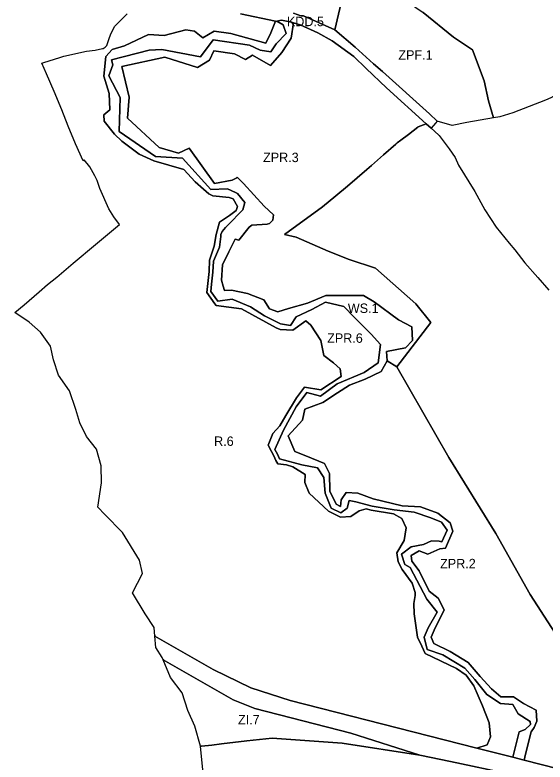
# Model space of a CAD drawing. Extents: x 7422965 to 7424741, y 5551047 to 5553849.
# Drawn here: x 7423382 to 7424058, y 5551939 to 5552892 of the extents above; entities that cross this region are included whole.
import ezdxf

# ---------------------------------------------------------------- set-up
doc = ezdxf.new("R2010")
doc.units = 0
for name, color, linetype in [('Default', 7, 'Continuous'), ('linie_rozgraniczajace', 7, 'Continuous'), ('oznaczenia_przeznaczen', 7, 'Continuous')]:
    doc.layers.add(name, color=color, linetype=linetype)

msp = doc.modelspace()

# ---------------------------------------------------------------- linework, layer by layer
at = {"layer": 'Default'}
for centre in [(7423560.61, 5552099.93), (7423571.24, 5552069.67)]:
    msp.add_circle(centre, 0.5, dxfattribs=at)
at = {"layer": 'linie_rozgraniczajace'}
for points in [[(7423790.23, 5552873.28), (7423799.43, 5552913.67), (7423849.34, 5552932.62), (7423902.73, 5552895.58), (7423941.64, 5552864.17), (7423966.03, 5552847.79), (7423980.88, 5552808.54), (7423986.42, 5552782.73), (7423992.54, 5552761.23), (7423958.43, 5552755.11), (7423939.86, 5552751.5), (7423920.85, 5552756.78), (7423910.83, 5552766.27), (7423850.81, 5552820.09), (7423839.55, 5552830.12), (7423816.12, 5552851.49)], [(7423518.12, 5552826.48), (7423573.2, 5552838.45), (7423614.8, 5552825.61), (7423630.31, 5552834.81), (7423635.93, 5552846.53), (7423662.15, 5552843.04), (7423676.01, 5552835.75), (7423684.91, 5552840.93), (7423708.24, 5552828.03), (7423722.4, 5552844.73), (7423734.34, 5552862.84), (7423737.47, 5552882.31), (7423745.99, 5552879.68), (7423768.55, 5552869.52), (7423786.65, 5552859.46), (7423814.43, 5552839.49), (7423830.33, 5552823.95), (7423856.04, 5552799.55), (7423906.82, 5552753.61), (7423900.02, 5552750.92), (7423896.58, 5552749.57), (7423896.01, 5552749.16), (7423884.16, 5552740.14), (7423874.28, 5552732.6), (7423869.69, 5552729.15), (7423868.14, 5552727.71), (7423852.28, 5552713.95), (7423836.83, 5552700.56), (7423830.95, 5552695.39), (7423806.47, 5552674.23), (7423791.37, 5552661.63), (7423774.44, 5552647.52), (7423725.87, 5552612.31), (7423740.76, 5552608.81), (7423781.67, 5552591), (7423808.46, 5552580.55), (7423841.86, 5552569.28), (7423893.7, 5552523.72), (7423912.7, 5552500.05), (7423869.36, 5552443.65), (7423856.77, 5552451.18), (7423856.17, 5552463.3), (7423880.19, 5552467.96), (7423889.14, 5552477.03), (7423888.44, 5552494.7), (7423871.43, 5552503.56), (7423840.28, 5552526.39), (7423826.71, 5552534.72), (7423778.85, 5552534.43), (7423755.2, 5552524.7), (7423731.19, 5552517.98), (7423717.3, 5552513.6), (7423706.78, 5552517.34), (7423699.33, 5552529.22), (7423678.68, 5552537.06), (7423658.18, 5552541.42), (7423649.45, 5552540.81), (7423647.6, 5552546.31), (7423645.4, 5552554.18), (7423646.92, 5552573.84), (7423654.67, 5552590.42), (7423662.8, 5552606.36), (7423667.83, 5552605.2), (7423680.9, 5552621.72), (7423684.32, 5552624.34), (7423703.8, 5552625.43), (7423706.94, 5552626.59), (7423711.13, 5552630.72), (7423711.75, 5552637.44), (7423700.08, 5552648.69), (7423673.64, 5552677.54), (7423665.53, 5552685.6), (7423665.02, 5552684.74), (7423659.29, 5552681.76), (7423636.4, 5552677.47), (7423604.33, 5552722.68), (7423590.57, 5552716.14), (7423565.78, 5552723.18), (7423525.68, 5552760.58), (7423527.6, 5552787.42)], [(7423571.24, 5552069.67), (7423660.42, 5552018.69), (7423687.98, 5552007.54), (7423810.5, 5551976.35), (7423898.81, 5551948.34), (7423799.44, 5551963.27), (7423710.11, 5551969.96), (7423677.82, 5551966.24), (7423645.54, 5551962.52), (7423633.28, 5551961.11), (7423619.89, 5551959.57), (7423618.77, 5551959.44), (7423611.64, 5551985.21), (7423602.59, 5552005.1), (7423595.36, 5552027.64), (7423580.3, 5552047.19)]]:
    msp.add_lwpolyline(points, close=True, dxfattribs=at)
for points in [[(7423799.43, 5552913.67), (7423790.23, 5552873.28), (7423750.07, 5552891.5), (7423746.77, 5552891.46), (7423737.23, 5552894.78)], [(7424119.81, 5552913.52), (7424124.09, 5552863.72), (7424127.86, 5552820.64), (7424065.95, 5552786.72), (7424059.13, 5552783.75), (7424017.18, 5552767.52), (7424000.77, 5552762.43), (7423992.54, 5552761.23), (7423986.42, 5552782.73), (7423980.88, 5552808.54), (7423966.03, 5552847.79), (7423941.64, 5552864.17), (7423902.73, 5552895.58)], [(7423381.92, 5552512.9), (7423393.91, 5552522.65), (7423412.78, 5552539.16), (7423423.51, 5552548.44), (7423435.26, 5552558.04), (7423456.27, 5552575.82), (7423484.66, 5552599.8), (7423515.49, 5552625.14), (7423508.29, 5552634.78), (7423501.59, 5552645.04), (7423490.22, 5552671.15), (7423486.78, 5552681.18), (7423483.94, 5552687.27), (7423477.67, 5552698.55), (7423470.41, 5552707.71), (7423469.11, 5552706.51), (7423459.04, 5552728.14), (7423449.78, 5552750.61), (7423441.58, 5552771.2), (7423431.88, 5552794.58), (7423422.17, 5552817.19), (7423416.17, 5552830.91), (7423418.6, 5552831.93), (7423439.05, 5552838.34), (7423444.5, 5552840.06), (7423473.12, 5552846.34), (7423484.14, 5552847.66), (7423493.67, 5552849.65), (7423494.7, 5552849.78), (7423497.14, 5552851.28), (7423499, 5552853.67), (7423501.89, 5552861.11), (7423504.32, 5552868.56), (7423509.48, 5552877.98), (7423514.86, 5552883.69), (7423525.29, 5552893.69)], [(7423669.78, 5552893.7), (7423714.41, 5552884.41), (7423708.37, 5552869.78), (7423701.9, 5552856.51), (7423657.37, 5552868.71), (7423636.23, 5552871.86), (7423621.57, 5552863.26), (7423611.21, 5552871.85), (7423600.14, 5552873.4), (7423572.41, 5552866.27), (7423552.34, 5552867.46), (7423521.9, 5552853.21), (7423506.07, 5552848.57), (7423498.01, 5552839.35), (7423495.57, 5552814.53), (7423502.35, 5552792.37), (7423503.2, 5552771.39), (7423495.45, 5552765.07), (7423495.77, 5552757.08), (7423508.86, 5552740.31), (7423518.42, 5552731.31), (7423540.62, 5552714.78), (7423559.29, 5552706.32), (7423597.36, 5552695.15), (7423612, 5552679.73), (7423622.4, 5552670.14), (7423629.4, 5552664.04), (7423634.65, 5552661.74), (7423655.49, 5552659.62), (7423660.35, 5552657.76), (7423665.97, 5552648.28), (7423664.14, 5552643.17), (7423655.79, 5552636.47), (7423643.12, 5552627.95), (7423638.76, 5552612.18), (7423636.35, 5552597.65), (7423630.36, 5552579.67), (7423629.65, 5552565.36), (7423626.74, 5552538.29), (7423636.81, 5552523.95), (7423638.6, 5552521.69), (7423671.12, 5552517.5), (7423715.17, 5552493.41), (7423720.55, 5552490.99), (7423736.41, 5552490.24), (7423753.3, 5552502.32), (7423759.54, 5552496.57), (7423772.34, 5552477.07), (7423776.11, 5552458.21), (7423788.5, 5552448.71), (7423796.82, 5552441.04), (7423798.22, 5552431.09), (7423772.48, 5552414.12), (7423751.48, 5552417.61), (7423741.39, 5552404.19), (7423727.56, 5552381.39), (7423719.88, 5552368.1)], [(7423737.23, 5552894.78), (7423746.77, 5552891.46), (7423750.07, 5552891.5), (7423790.23, 5552873.28), (7423816.12, 5552851.49), (7423839.55, 5552830.12), (7423850.81, 5552820.09), (7423910.83, 5552766.27), (7423920.85, 5552756.78), (7423918.68, 5552754.4), (7423913.08, 5552747.94), (7423906.82, 5552753.61), (7423856.04, 5552799.55), (7423830.33, 5552823.95), (7423814.43, 5552839.49), (7423786.65, 5552859.46), (7423768.55, 5552869.52), (7423745.99, 5552879.68), (7423737.47, 5552882.31), (7423734.65, 5552883.18), (7423722.04, 5552885.93), (7423715.99, 5552884.44), (7423715.19, 5552884.25), (7423714.41, 5552884.41), (7423669.78, 5552893.7)], [(7423495.77, 5552757.08), (7423495.45, 5552765.07), (7423503.2, 5552771.39), (7423502.35, 5552792.37), (7423495.57, 5552814.53), (7423498.01, 5552839.35), (7423506.07, 5552848.57), (7423521.9, 5552853.21), (7423552.34, 5552867.46), (7423572.41, 5552866.27), (7423600.14, 5552873.4), (7423611.21, 5552871.85), (7423621.57, 5552863.26), (7423636.23, 5552871.86), (7423657.37, 5552868.71), (7423701.9, 5552856.51), (7423708.37, 5552869.78), (7423714.41, 5552884.41), (7423715.19, 5552884.25), (7423715.99, 5552884.44), (7423724.12, 5552879.63), (7423728.09, 5552868.86), (7423715.36, 5552855.64), (7423708.53, 5552845.33), (7423694.97, 5552847.44), (7423681.31, 5552853.85), (7423634.95, 5552860.82), (7423618.89, 5552838.84), (7423569.19, 5552848.56), (7423553, 5552847.71), (7423504.95, 5552835.26), (7423506.66, 5552828.62), (7423501.73, 5552814.95), (7423516.28, 5552787.25), (7423514.81, 5552743.76), (7423561.23, 5552711.88), (7423595.84, 5552709.54), (7423631.86, 5552669.82), (7423652.56, 5552670.42), (7423655.99, 5552669.55), (7423665.93, 5552664.56), (7423675.13, 5552653.05), (7423672.8, 5552643.86), (7423653.55, 5552624.23), (7423650.7, 5552621.08), (7423646.49, 5552616.25), (7423644.52, 5552612.31), (7423644.59, 5552610.02), (7423643.13, 5552596.36), (7423635.3, 5552578.5), (7423634.57, 5552564.46), (7423632.73, 5552549.12), (7423631.88, 5552539.69), (7423640.87, 5552527.11), (7423659.2, 5552530.04), (7423682.56, 5552520.23), (7423700.48, 5552508.65), (7423720.76, 5552498.26), (7423733.62, 5552496.4), (7423740.79, 5552507.45), (7423760.88, 5552516.48), (7423778.28, 5552526.14), (7423801.75, 5552520.67), (7423815.43, 5552506.41), (7423836.5, 5552485.18), (7423848.28, 5552471.98), (7423845.61, 5552448.56), (7423827.57, 5552436.21), (7423793.23, 5552421.73), (7423771.95, 5552405.92), (7423754.3, 5552410.96), (7423741.01, 5552392.42), (7423724.64, 5552362.81), (7423713.56, 5552337.91), (7423716.78, 5552332.11), (7423719.42, 5552326.32), (7423748.14, 5552318.52), (7423768.09, 5552314.6), (7423776.1, 5552302.24), (7423777.86, 5552282.4), (7423785.4, 5552263.16), (7423797.61, 5552257.43), (7423806.09, 5552263.18), (7423808.26, 5552273.19), (7423816.95, 5552271.36), (7423837.6, 5552265.74), (7423865.9, 5552261.08), (7423891.32, 5552258.33), (7423912.44, 5552250.92), (7423926.36, 5552245.41), (7423933.33, 5552235.37), (7423926.66, 5552220.14), (7423923.13, 5552221.11), (7423913.64, 5552221.44), (7423903.45, 5552216.88), (7423887.49, 5552214.09), (7423875.1, 5552204.48), (7423879.67, 5552191.32), (7423886.42, 5552187.66), (7423907.58, 5552147.01)], [(7423501.73, 5552814.95), (7423506.66, 5552828.62), (7423504.95, 5552835.26), (7423553, 5552847.71), (7423569.19, 5552848.56), (7423618.89, 5552838.84), (7423634.95, 5552860.82), (7423681.31, 5552853.85), (7423694.97, 5552847.44), (7423708.53, 5552845.33), (7423715.36, 5552855.64), (7423728.09, 5552868.86), (7423724.12, 5552879.63), (7423715.99, 5552884.44), (7423722.04, 5552885.93), (7423734.65, 5552883.18), (7423737.47, 5552882.31), (7423734.34, 5552862.84), (7423722.4, 5552844.73), (7423708.24, 5552828.03), (7423684.91, 5552840.93), (7423676.01, 5552835.75), (7423662.15, 5552843.04), (7423635.93, 5552846.53), (7423630.31, 5552834.81), (7423614.8, 5552825.61), (7423573.2, 5552838.45), (7423518.12, 5552826.48), (7423527.6, 5552787.42), (7423525.68, 5552760.58), (7423565.78, 5552723.18), (7423590.57, 5552716.14), (7423604.33, 5552722.68), (7423636.4, 5552677.47), (7423659.29, 5552681.76), (7423665.02, 5552684.74), (7423665.53, 5552685.6), (7423673.64, 5552677.54), (7423700.08, 5552648.69), (7423711.75, 5552637.44), (7423711.13, 5552630.72), (7423706.94, 5552626.59), (7423703.8, 5552625.43), (7423684.32, 5552624.34), (7423680.9, 5552621.72), (7423667.83, 5552605.2), (7423662.8, 5552606.36), (7423654.67, 5552590.42), (7423646.92, 5552573.84), (7423645.4, 5552554.18), (7423647.6, 5552546.31), (7423649.45, 5552540.81), (7423658.18, 5552541.42), (7423678.68, 5552537.06), (7423699.33, 5552529.22), (7423706.78, 5552517.34), (7423717.3, 5552513.6), (7423731.19, 5552517.98), (7423755.2, 5552524.7), (7423778.85, 5552534.43), (7423826.71, 5552534.72), (7423840.28, 5552526.39), (7423871.43, 5552503.56), (7423888.44, 5552494.7), (7423889.14, 5552477.03), (7423880.19, 5552467.96), (7423856.17, 5552463.3), (7423856.77, 5552451.18), (7423849.24, 5552437.64), (7423828.99, 5552427.81), (7423808.65, 5552420.26), (7423793.42, 5552410.29), (7423774.82, 5552397.91), (7423763.47, 5552393.94), (7423751.7, 5552389.44), (7423749.03, 5552375.31), (7423730.47, 5552355.5), (7423738.91, 5552335.44), (7423753, 5552330.02), (7423777.12, 5552320.16), (7423783.51, 5552307.61), (7423783.55, 5552284.87), (7423791.78, 5552268.26), (7423797.33, 5552265.52), (7423798.36, 5552273.72), (7423804.73, 5552283.13), (7423819.42, 5552282.47), (7423839.06, 5552274.98), (7423876.01, 5552266.1), (7423899.37, 5552265.11), (7423921.38, 5552256.76), (7423937.24, 5552244.36), (7423940.53, 5552233.8), (7423931.54, 5552212.19), (7423924.28, 5552211.5), (7423908.87, 5552204.75), (7423897.68, 5552208.99), (7423887.35, 5552202.71), (7423888.52, 5552195.81), (7423897.92, 5552183.41)], [(7423631.86, 5552669.82), (7423595.84, 5552709.54), (7423561.23, 5552711.88), (7423514.81, 5552743.76), (7423516.28, 5552787.25), (7423501.73, 5552814.95)], [(7423907.58, 5552147.01), (7423920.57, 5552130.57), (7423909.34, 5552110.5), (7423904, 5552098.61), (7423908.13, 5552083), (7423928.02, 5552075.95), (7423956.18, 5552059.32), (7423968.77, 5552044.8), (7423984.28, 5552025.67), (7424001.51, 5552013.86), (7424017.3, 5552012.88), (7424024.18, 5552000.72), (7424039.31, 5551991.14), (7424040.01, 5551987.27), (7424032.89, 5551980.96), (7424025.26, 5551977.97), (7424017.68, 5551947.36), (7424017.17, 5551945.4), (7423971.53, 5551957.02), (7423984.41, 5551961.28), (7423989, 5551971.47), (7423987.27, 5551989.41), (7423978.39, 5552011.07), (7423967.34, 5552036.64), (7423957.78, 5552050.26), (7423945.43, 5552058.77), (7423905.55, 5552077.93), (7423901.25, 5552087), (7423895.77, 5552098.79), (7423891.56, 5552128.64), (7423891.03, 5552141.63), (7423892.62, 5552151.7), (7423892.5, 5552154.7), (7423892.46, 5552155.7), (7423888.98, 5552167.56), (7423876.26, 5552185.06), (7423870.86, 5552194.85), (7423869.2, 5552206.23), (7423878.75, 5552222.19), (7423881.1, 5552238.3), (7423875.62, 5552250.09), (7423865.22, 5552256.12), (7423836.53, 5552260.85), (7423830.09, 5552262.25), (7423821.18, 5552259.89), (7423810.47, 5552252.45), (7423797.49, 5552251.92), (7423782.17, 5552259.31), (7423769.7, 5552270.81), (7423757.22, 5552282.31), (7423751.66, 5552296.1), (7423752.25, 5552306.13), (7423736.63, 5552315.97), (7423728.5, 5552318.32), (7423717.24, 5552319.9), (7423714.95, 5552324.08), (7423712.32, 5552329.86), (7423709.14, 5552335.56), (7423705.12, 5552343.43), (7423711.1, 5552358.5), (7423719.88, 5552368.1), (7423727.56, 5552381.39), (7423741.39, 5552404.19), (7423751.48, 5552417.61), (7423772.48, 5552414.12), (7423798.22, 5552431.09), (7423796.82, 5552441.04), (7423788.5, 5552448.71), (7423776.11, 5552458.21), (7423772.34, 5552477.07), (7423759.54, 5552496.57), (7423753.3, 5552502.32), (7423736.41, 5552490.24), (7423720.55, 5552490.99), (7423715.17, 5552493.41), (7423671.12, 5552517.5), (7423638.6, 5552521.69), (7423636.81, 5552523.95), (7423626.74, 5552538.29), (7423629.65, 5552565.36), (7423630.36, 5552579.67), (7423636.35, 5552597.65), (7423638.76, 5552612.18), (7423643.12, 5552627.95), (7423655.79, 5552636.47), (7423664.14, 5552643.17), (7423665.97, 5552648.28), (7423660.35, 5552657.76), (7423655.49, 5552659.62), (7423634.65, 5552661.74), (7423629.4, 5552664.04), (7423622.4, 5552670.14), (7423612, 5552679.73), (7423597.36, 5552695.15), (7423559.29, 5552706.32), (7423540.62, 5552714.78), (7423518.42, 5552731.31), (7423508.86, 5552740.31), (7423495.77, 5552757.08)], [(7424089.19, 5552076.05), (7424039.42, 5552153.32), (7423995.71, 5552231.1), (7423935.73, 5552327.89), (7423869.36, 5552443.65), (7423912.7, 5552500.05), (7423893.7, 5552523.72), (7423841.86, 5552569.28), (7423808.46, 5552580.55), (7423781.67, 5552591), (7423740.76, 5552608.81), (7423725.87, 5552612.31), (7423774.44, 5552647.52), (7423791.37, 5552661.63), (7423806.47, 5552674.23), (7423830.95, 5552695.39), (7423836.83, 5552700.56), (7423852.28, 5552713.95), (7423868.14, 5552727.71), (7423869.69, 5552729.15), (7423874.28, 5552732.6), (7423884.16, 5552740.14), (7423896.01, 5552749.16), (7423896.58, 5552749.57), (7423900.02, 5552750.92), (7423906.82, 5552753.61), (7423913.08, 5552747.94), (7423917.16, 5552744.25), (7423923.26, 5552738.78), (7423936.05, 5552721.84), (7423943.57, 5552710.44), (7423948.13, 5552700.78), (7423968.75, 5552667.08), (7423981.44, 5552643.95), (7423996.22, 5552621.82), (7424012.77, 5552601.21), (7424019.93, 5552592.98), (7424032.56, 5552576.3), (7424049.23, 5552557.69), (7424063.4, 5552541.4)], [(7423897.92, 5552183.41), (7423910.41, 5552157.37), (7423921.95, 5552148.62), (7423929.69, 5552133.46), (7423917.09, 5552107.71), (7423912.99, 5552098.51), (7423916.62, 5552090.57), (7423937.52, 5552080.46), (7423960.41, 5552066.2), (7423975.43, 5552048.48), (7423990, 5552032.9), (7424001.99, 5552022.6), (7424018.06, 5552022.7), (7424031.11, 5552013.9), (7424047.25, 5552005.6), (7424047.8, 5551991.71), (7424044.62, 5551983.49), (7424040.76, 5551977.72), (7424033.55, 5551949.56), (7424031.65, 5551941.72), (7424017.17, 5551945.4), (7424017.68, 5551947.36), (7424025.26, 5551977.97), (7424032.89, 5551980.96), (7424040.01, 5551987.27), (7424039.31, 5551991.14), (7424024.18, 5552000.72), (7424017.3, 5552012.88), (7424001.51, 5552013.86), (7423984.28, 5552025.67), (7423968.77, 5552044.8), (7423956.18, 5552059.32), (7423928.02, 5552075.95), (7423908.13, 5552083), (7423904, 5552098.61), (7423909.34, 5552110.5), (7423920.57, 5552130.57), (7423907.58, 5552147.01), (7423886.42, 5552187.66), (7423879.67, 5552191.32), (7423875.1, 5552204.48), (7423887.49, 5552214.09), (7423903.45, 5552216.88), (7423913.64, 5552221.44), (7423923.13, 5552221.11), (7423926.66, 5552220.14), (7423933.33, 5552235.37), (7423926.36, 5552245.41), (7423912.44, 5552250.92), (7423891.32, 5552258.33), (7423865.9, 5552261.08), (7423837.6, 5552265.74), (7423816.95, 5552271.36), (7423808.26, 5552273.19), (7423806.09, 5552263.18), (7423797.61, 5552257.43), (7423785.4, 5552263.16), (7423777.86, 5552282.4), (7423776.1, 5552302.24), (7423768.09, 5552314.6), (7423748.14, 5552318.52), (7423719.42, 5552326.32), (7423716.78, 5552332.11), (7423713.56, 5552337.91), (7423724.64, 5552362.81), (7423741.01, 5552392.42), (7423754.3, 5552410.96), (7423771.95, 5552405.92), (7423793.23, 5552421.73), (7423827.57, 5552436.21), (7423845.61, 5552448.56), (7423848.28, 5552471.98), (7423836.5, 5552485.18), (7423815.43, 5552506.41), (7423801.75, 5552520.67), (7423778.28, 5552526.14), (7423760.88, 5552516.48), (7423740.79, 5552507.45), (7423733.62, 5552496.4), (7423720.76, 5552498.26), (7423700.48, 5552508.65), (7423682.56, 5552520.23), (7423659.2, 5552530.04), (7423640.87, 5552527.11), (7423631.88, 5552539.69), (7423632.73, 5552549.12), (7423634.57, 5552564.46), (7423635.3, 5552578.5), (7423643.13, 5552596.36), (7423644.59, 5552610.02), (7423644.52, 5552612.31), (7423646.49, 5552616.25), (7423650.7, 5552621.08), (7423653.55, 5552624.23), (7423672.8, 5552643.86), (7423675.13, 5552653.05), (7423665.93, 5552664.56), (7423655.99, 5552669.55), (7423652.56, 5552670.42), (7423631.86, 5552669.82)], [(7423719.88, 5552368.1), (7423711.1, 5552358.5), (7423705.12, 5552343.43), (7423709.14, 5552335.56), (7423712.32, 5552329.86), (7423714.95, 5552324.08), (7423717.24, 5552319.9), (7423728.5, 5552318.32), (7423736.63, 5552315.97), (7423752.25, 5552306.13), (7423751.66, 5552296.1), (7423757.22, 5552282.31), (7423769.7, 5552270.81), (7423782.17, 5552259.31), (7423797.49, 5552251.92), (7423810.47, 5552252.45), (7423821.18, 5552259.89), (7423830.09, 5552262.25), (7423836.53, 5552260.85), (7423865.22, 5552256.12), (7423875.62, 5552250.09), (7423881.1, 5552238.3), (7423878.75, 5552222.19), (7423869.2, 5552206.23), (7423870.86, 5552194.85), (7423876.26, 5552185.06), (7423888.98, 5552167.56), (7423892.46, 5552155.7), (7423892.5, 5552154.7), (7423892.62, 5552151.7), (7423891.03, 5552141.63), (7423891.56, 5552128.64), (7423895.77, 5552098.79), (7423901.25, 5552087), (7423905.55, 5552077.93), (7423945.43, 5552058.77), (7423957.78, 5552050.26), (7423967.34, 5552036.64), (7423978.39, 5552011.07), (7423987.27, 5551989.41), (7423989, 5551971.47), (7423984.41, 5551961.28), (7423971.53, 5551957.02), (7423909.82, 5551972.73), (7423733.12, 5552017.72), (7423682.74, 5552034.24), (7423635.05, 5552057.38), (7423560.61, 5552099.93), (7423559.63, 5552110.84), (7423548.09, 5552128.24), (7423532.03, 5552155.08), (7423544.84, 5552179.8), (7423540.87, 5552196.78), (7423519.32, 5552232.11), (7423496.59, 5552255.03), (7423487.55, 5552264.39), (7423492.26, 5552295.48), (7423491.96, 5552317.16), (7423485.99, 5552338.67), (7423473.29, 5552354.87), (7423464.9, 5552372), (7423459.64, 5552389.07), (7423451.69, 5552412.97), (7423437.65, 5552433.05), (7423431.3, 5552452.36), (7423427.43, 5552469.71), (7423414.33, 5552487.73), (7423400.23, 5552500.4), (7423381.92, 5552512.9)], [(7424116.88, 5551920.02), (7424031.65, 5551941.72), (7424033.55, 5551949.56), (7424040.76, 5551977.72), (7424044.62, 5551983.49), (7424047.8, 5551991.71), (7424047.25, 5552005.6), (7424031.11, 5552013.9), (7424018.06, 5552022.7), (7424001.99, 5552022.6), (7423990, 5552032.9), (7423975.43, 5552048.48), (7423960.41, 5552066.2), (7423937.52, 5552080.46), (7423916.62, 5552090.57), (7423912.99, 5552098.51), (7423917.09, 5552107.71), (7423929.69, 5552133.46), (7423921.95, 5552148.62), (7423910.41, 5552157.37), (7423897.92, 5552183.41), (7423888.52, 5552195.81), (7423887.35, 5552202.71), (7423897.68, 5552208.99), (7423908.87, 5552204.75), (7423924.28, 5552211.5), (7423931.54, 5552212.19), (7423940.53, 5552233.8), (7423937.24, 5552244.36), (7423921.38, 5552256.76), (7423899.37, 5552265.11), (7423876.01, 5552266.1), (7423839.06, 5552274.98), (7423819.42, 5552282.47), (7423804.73, 5552283.13), (7423798.36, 5552273.72), (7423797.33, 5552265.52), (7423791.78, 5552268.26), (7423783.55, 5552284.87), (7423783.51, 5552307.61), (7423777.12, 5552320.16), (7423753, 5552330.02), (7423738.91, 5552335.44), (7423730.47, 5552355.5), (7423749.03, 5552375.31), (7423751.7, 5552389.44), (7423763.47, 5552393.94), (7423774.82, 5552397.91), (7423793.42, 5552410.29), (7423808.65, 5552420.26), (7423828.99, 5552427.81), (7423849.24, 5552437.64), (7423856.77, 5552451.18), (7423869.36, 5552443.65), (7423935.73, 5552327.89), (7423995.71, 5552231.1), (7424039.42, 5552153.32), (7424089.19, 5552076.05)], [(7424014.01, 5551923.99), (7423937.85, 5551940.09), (7423898.81, 5551948.34), (7423810.5, 5551976.35), (7423687.98, 5552007.54), (7423660.42, 5552018.69), (7423571.24, 5552069.67), (7423570.01, 5552072.73), (7423570.01, 5552072.73), (7423561.93, 5552085.33), (7423560.61, 5552099.93), (7423635.05, 5552057.38), (7423682.74, 5552034.24), (7423733.12, 5552017.72), (7423909.82, 5551972.73), (7423971.53, 5551957.02), (7424017.17, 5551945.4), (7424031.65, 5551941.72), (7424116.88, 5551920.02)], [(7423622.43, 5551920.96), (7423618.77, 5551959.44), (7423619.89, 5551959.57), (7423633.28, 5551961.11), (7423645.54, 5551962.52), (7423677.82, 5551966.24), (7423710.11, 5551969.96), (7423799.44, 5551963.27), (7423898.81, 5551948.34), (7423937.85, 5551940.09), (7424014.01, 5551923.99)]]:
    msp.add_lwpolyline(points, dxfattribs=at)

# ---------------------------------------------------------------- texts
at = {"layer": 'oznaczenia_przeznaczen'}
for s, p in [('KDD.5', (7423728.98, 5552878.11)), ('ZPF.1', (7423871.26, 5552835.46)), ('ZPR.3', (7423698.56, 5552704.73)), ('WS.1', (7423806.74, 5552512.31)), ('ZPR.6', (7423780.36, 5552474.23)), ('R.6', (7423636.08, 5552342.72)), ('ZPR.2', (7423924.48, 5552186.57)), ('ZI.7', (7423666.57, 5551987.52))]:
    msp.add_text(s, height=12, dxfattribs=at).set_placement(p)

doc.saveas('drawing.dxf')
